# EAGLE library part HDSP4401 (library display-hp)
LED DISPLAY 1-character dot matrix without decimal point
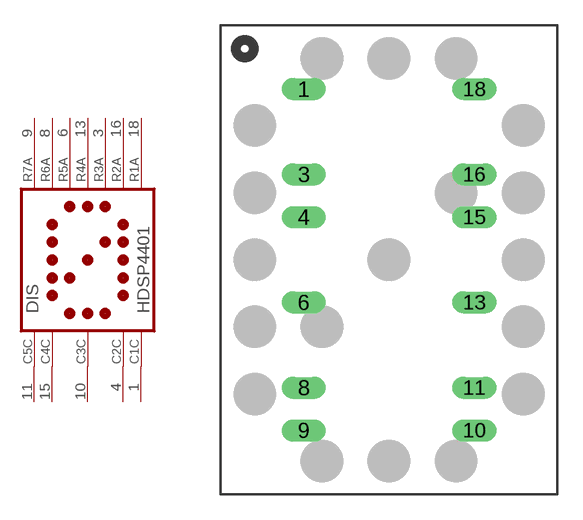
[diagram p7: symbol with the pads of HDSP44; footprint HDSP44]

Designator prefix DIS

## HDSP4401 (OC_FARNELL: unknown; OC_NEWARK: unknown)  [HDSP44]
1  C1C  pas
3  R3A  pas
4  C2C  pas
6  R5A  pas
8  R6A  pas
9  R7A  pas
10  C3C  pas
11  C5C  pas
13  R4A  pas
15  C4C  pas
16  R2A  pas
18  R1A  pas

## Footprint HDSP44 (pad centres in mm)
LED DISPLAY 27-mm 1 character dot matrix without decimal point
drill 0.813 long: 1 -5.08,10.16; 3 -5.08,5.08; 4 -5.08,2.54; 6 -5.08,-2.54; 8 -5.08,-7.62; 9 -5.08,-10.16; 10 5.08,-10.16; 11 5.08,-7.62; 13 5.08,-2.54; 15 5.08,2.54; 16 5.08,5.08; 18 5.08,10.16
